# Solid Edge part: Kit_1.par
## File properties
Sűrűség: 0,000 kg/m^3
Pontosság: 0,990
Author: ahadarics
Last saved by: psaghy
Revision: 77
Username: ahadarics
Dokumentum tartalom típus: 0
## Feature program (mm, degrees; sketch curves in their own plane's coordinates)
base feature "unnamed BaseFeature 1"
sketch for "Furat_1" plane through (0, 0, 37) normal (0, 0, 1) x-axis (0, -1, 0)
  hole centre (-19, 19) bore radius 2.4585
hole "Furat_1" nominal diameter 6 finite  VBottomAngle = 118 deg; ThreadDepth = 16 mm
sketch for "unnamed Hole 1" plane through (0, 0, 37) normal (0, 0, 1) x-axis (0, -1, 0)
  hole centre (-19, -19) bore radius 2.4585
hole "unnamed Hole 1" finite
sketch for "unnamed Hole 2" plane through (0, 0, 37) normal (0, 0, 1) x-axis (0, -1, 0)
  hole centre (19, -19) bore radius 2.4585
hole "unnamed Hole 2" finite
sketch for "unnamed Hole 3" plane through (0, 0, 37) normal (0, 0, 1) x-axis (0, -1, 0)
  hole centre (19, 19) bore radius 2.4585
hole "unnamed Hole 3" finite
pattern "unnamed Pattern 1" of "Furat_1", "unnamed Hole 1", "unnamed Hole 2", "unnamed Hole 3"
sketch for "Furat_5" plane through (27.25, 0, 19.2488) normal (1, 0, 0) x-axis (0, 0, -1)
hole "Furat_5" diameter 13.157 finite  ThreadDepth = 12 mm
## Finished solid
Body 1: solid body, 370 faces, 887 edges, 570 vertices, 3 internal voids.
  Faces by surface: plane 146, cylinder 97, cone 43, torus 38, spline 31, sphere 9, swept 6
  Edges by curve: line 365, circle 310, curve on surface 184, spline 28
Bounding box of the edges (mm; curved faces can reach further): 54.500 x 54.500 x 53.000, from (-27.25, -27.25, 6) to (27.25, 27.25, 59).
Cylindrical faces by radius (mm): R0.2344 x1, R0.4113 x1, R0.4771 x1, R0.5 x7, R0.5094 x1, R0.5226 x1, R0.5534 x1, R0.6836 x1, R0.7041 x1, R0.7049 x1, R0.7519 x1, R0.7795 x1, R0.7904 x1, R0.8051 x1, R0.824 x1, R0.8903 x1, R0.9421 x1, R0.9541 x2, R1 x12, R1.0216 x1, R1.0284 x1, R1.25 x1, R1.2857 x1, R2.4585 x8, R3 x4, R3.1 x4, R3.5 x1, R4.95 x1, R5 x7, R5.15 x4, R5.72 x1, R5.7225 x1, R7.5 x1, R8 x1, R8.25 x4, R8.3 x1, R8.4 x1, R8.4236 x1, R8.7 x1, R10 x2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
Conical faces (half-angle, radius in mm at the cone's reference point): 1.6538 deg R9.75 x1, 3.5477 deg R10.7454 x1, 5.762 deg R8.4 x1, 11.1239 deg R8.0056 x1, 15 deg R16.1406 x1, 15.3654 deg R8.7214 x1, 19.3654 deg R9.1921 x1, 25.0169 deg R12.31 x1, 29.0546 deg R23.75 x4, 30 deg R5.1443 x1, 30 deg R9.8557 x2, 30 deg R10.1443 x1, 30 deg R17 x1, 45 deg R2.75 x1, 45 deg R2.825 x1, 45 deg R3.25 x8, 45 deg R4.85 x8, 45 deg R6.72 x1, 45 deg R8.15 x2, 45 deg R13.25 x1, 59 deg R2.4585 x4
Toroidal faces (ring radius, tube radius in mm): R0.9686 r0.5 x1, R1.4708 r0.5006 x3, R3.3 r0.3 x4, R4.7 r0.3 x1, R4.95 r0.2 x4, R5.65 r0.5 x4, R8.3 r0.3 x1, R8.3085 r0.3 x1, R8.75 r0.5 x2, R9.4279 r0.25 x1, R9.5 r0.5 x1, R10.2464 r0.5 x1, R12.8 r0.2 x1, R14.5 r2 x1, R15.3663 r0.5 x1, R18 r0.5 x1, R22 r1 x3, R26.5 r1 x6, R27.7942 r0.5 x1
Spherical faces by radius (mm): R0.5 x3, R1 x6
Planar faces by outward normal: +x 26, +y 10, +z 32, -x 5, -y 9, -z 22, oblique 42
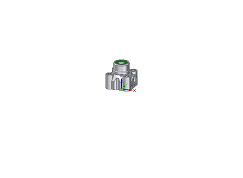
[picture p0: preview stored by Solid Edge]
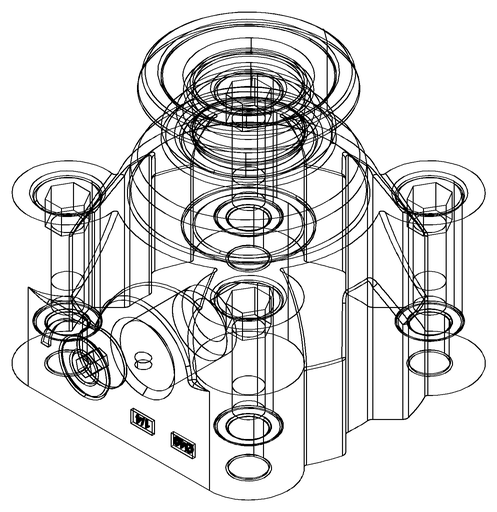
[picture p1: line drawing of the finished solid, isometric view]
